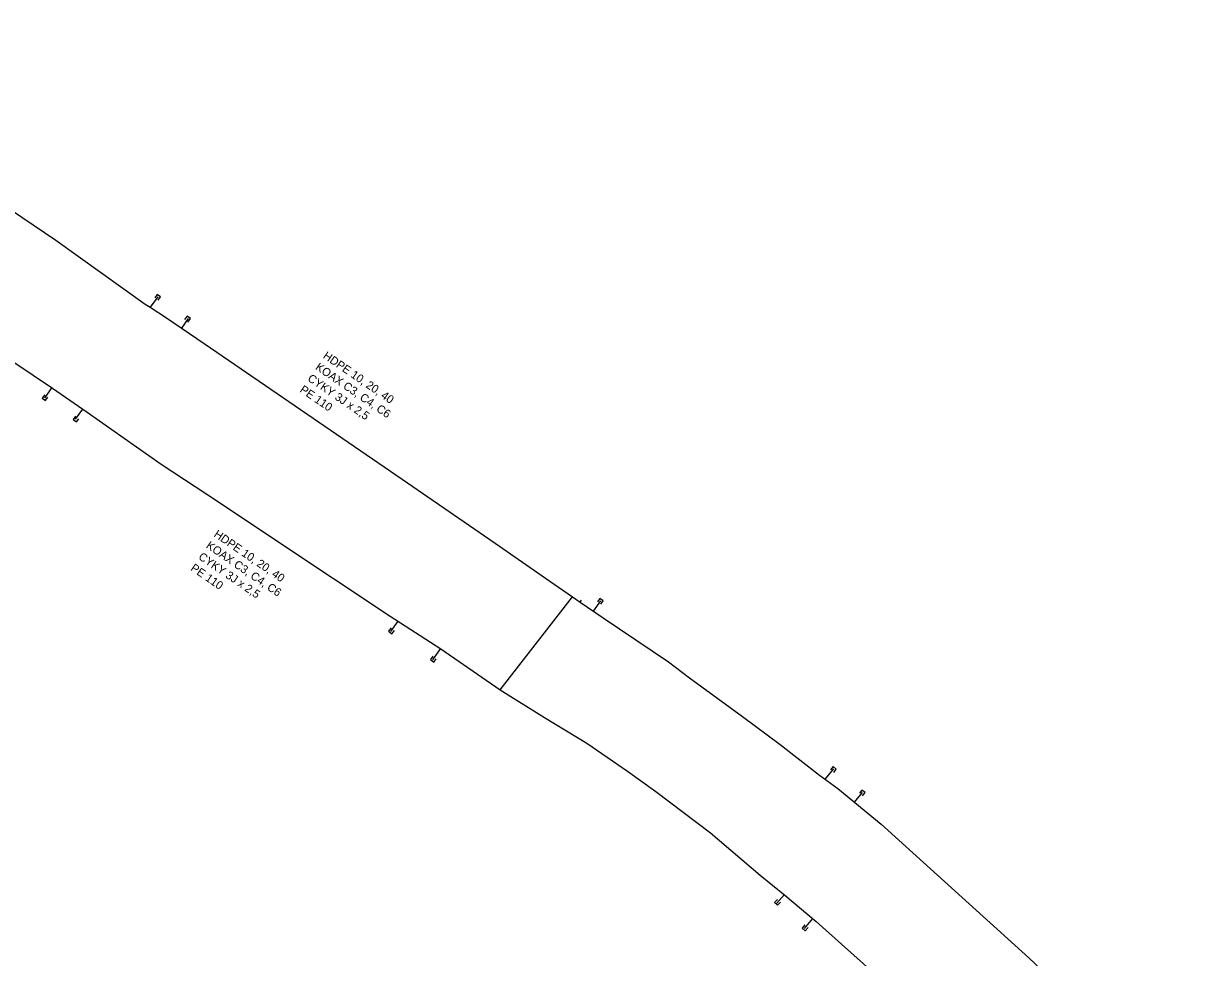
# Model space of a CAD drawing. Extents: x -651943 to -618711, y -1138561 to -1100552.
# Drawn here: x -641955 to -641849.2, y -1113561 to -1113475.7 of the extents above; entities that cross this region are included whole.
import ezdxf

# ---------------------------------------------------------------- set-up
doc = ezdxf.new("R2010")
doc.units = 0
for name, color, linetype in [('KT optika', 7, 'Continuous'), ('KT trasa', 7, 'Continuous'), ('KT zařízení', 7, 'Continuous')]:
    doc.layers.add(name, color=color, linetype=linetype)

# ---------------------------------------------------------------- blocks, each defined once
blk = doc.blocks.new('KKK_4')
at = {"layer": 'KT zařízení'}
for p, q in [((0.037, 0.037), (-0.038, 0.037)), ((0.037, -0.038), (0.037, 0.037)), ((-0.038, -0.038), (0.037, -0.038))]:
    blk.add_line(p, q, dxfattribs=at)
blk = doc.blocks.new('KKK_5')
at = {"layer": 'KT zařízení'}
for p, q in [((0.037, 0.037), (-0.038, 0.038)), ((0.037, -0.037), (0.037, 0.037)), ((-0.037, -0.037), (0.037, -0.037))]:
    blk.add_line(p, q, dxfattribs=at)
blk = doc.blocks.new('KKK_6')
at = {"layer": 'KT zařízení'}
for p, q in [((0.038, 0.038), (-0.038, 0.038)), ((0.038, -0.038), (0.038, 0.038)), ((-0.038, -0.037), (0.038, -0.038))]:
    blk.add_line(p, q, dxfattribs=at)
blk = doc.blocks.new('KKK_7')
at = {"layer": 'KT zařízení'}
for p, q in [((0.038, 0.037), (-0.038, 0.037)), ((0.038, -0.037), (0.038, 0.037)), ((-0.038, -0.038), (0.038, -0.037))]:
    blk.add_line(p, q, dxfattribs=at)
blk = doc.blocks.new('KKK_8')
at = {"layer": 'KT zařízení'}
for p, q in [((0.037, 0.037), (-0.038, 0.037)), ((0.038, -0.038), (0.037, 0.037)), ((-0.038, -0.037), (0.038, -0.038))]:
    blk.add_line(p, q, dxfattribs=at)
blk = doc.blocks.new('KKK_10')
at = {"layer": 'KT zařízení'}
for p, q in [((0.037, 0.037), (-0.037, 0.038)), ((0.037, -0.037), (0.037, 0.037)), ((-0.038, -0.037), (0.037, -0.037))]:
    blk.add_line(p, q, dxfattribs=at)
blk = doc.blocks.new('KKK_2')
at = {"layer": 'KT zařízení'}
for p, q in [((0.037, 0.038), (-0.037, 0.038)), ((0.037, -0.038), (0.037, 0.038)), ((-0.037, -0.038), (0.037, -0.038))]:
    blk.add_line(p, q, dxfattribs=at)
blk = doc.blocks.new('KKK_11')
at = {"layer": 'KT zařízení'}
for p, q in [((0.038, 0.037), (-0.037, 0.037)), ((0.038, -0.037), (0.038, 0.037)), ((-0.038, -0.037), (0.038, -0.037))]:
    blk.add_line(p, q, dxfattribs=at)

msp = doc.modelspace()

# ---------------------------------------------------------------- linework, layer by layer
at = {"layer": 'KT optika'}
for points in [[(-641981.59, -1113475.66), (-641978.35, -1113477.8), (-641973.39, -1113481.09), (-641965.85, -1113486.26), (-641958.24, -1113491.27), (-641951.99, -1113495.48), (-641943.83, -1113501.31), (-641943.42, -1113501.58)], [(-641980.53, -1113490.04), (-641975.1, -1113493.79), (-641970.07, -1113497.16), (-641964.3, -1113501.02), (-641959.29, -1113504.31), (-641952.31, -1113509), (-641949.13, -1113511.18), (-641942.39, -1113515.92), (-641937.14, -1113519.38), (-641931.83, -1113522.95), (-641921.48, -1113529.82), (-641916.84, -1113532.81), (-641911.44, -1113536.54)], [(-641943.38, -1113501.61), (-641941.89, -1113502.58), (-641938.46, -1113504.92), (-641933.44, -1113508.37), (-641920.38, -1113517.31), (-641911.88, -1113523.16), (-641906.9, -1113526.63), (-641904.82, -1113528.06)], [(-641911.44, -1113536.54), (-641904.82, -1113528.06)], [(-641904.82, -1113528.06), (-641904.13, -1113528.53)], [(-641904.13, -1113528.53), (-641902.04, -1113529.97), (-641896.07, -1113533.99), (-641894.16, -1113535.44), (-641889.3, -1113538.97), (-641885.87, -1113541.54), (-641882.27, -1113544.34), (-641880.61, -1113545.54), (-641876.66, -1113548.82), (-641872.16, -1113552.88), (-641863.18, -1113561.02), (-641860.34, -1113563.69), (-641857.88, -1113566.01), (-641856.08, -1113567.88), (-641849.41, -1113574.94)], [(-641911.44, -1113536.54), (-641907.38, -1113539.08), (-641903.51, -1113541.41), (-641899.81, -1113543.96), (-641897.22, -1113545.82), (-641892.23, -1113549.61), (-641887.7, -1113553.48), (-641885.43, -1113555.29), (-641882.57, -1113557.7), (-641877.1, -1113562.6), (-641871.4, -1113567.76), (-641866.6, -1113572.39), (-641861.74, -1113577.24), (-641857.57, -1113581.74), (-641851.66, -1113588.43), (-641849.2, -1113591.22)]]:
    msp.add_lwpolyline(points, dxfattribs=at)
at = {"layer": 'KT trasa'}
for points in [[(-641981.59, -1113475.66), (-641978.35, -1113477.8), (-641973.39, -1113481.09), (-641965.85, -1113486.26), (-641958.24, -1113491.27), (-641951.99, -1113495.48), (-641943.83, -1113501.31), (-641943.42, -1113501.58)], [(-641980.53, -1113490.04), (-641975.1, -1113493.79), (-641970.07, -1113497.16), (-641964.3, -1113501.02), (-641959.29, -1113504.31), (-641952.31, -1113509), (-641949.13, -1113511.18), (-641942.39, -1113515.92), (-641937.14, -1113519.38), (-641931.83, -1113522.95), (-641921.48, -1113529.82), (-641916.84, -1113532.81), (-641911.44, -1113536.54)], [(-641943.38, -1113501.61), (-641941.89, -1113502.58), (-641938.46, -1113504.92), (-641933.44, -1113508.37), (-641920.38, -1113517.31), (-641911.88, -1113523.16), (-641906.9, -1113526.63), (-641904.82, -1113528.06)], [(-641911.44, -1113536.54), (-641904.82, -1113528.06)], [(-641904.82, -1113528.06), (-641904.13, -1113528.53)], [(-641904.13, -1113528.53), (-641902.04, -1113529.97), (-641896.07, -1113533.99), (-641894.16, -1113535.44), (-641889.3, -1113538.97), (-641885.87, -1113541.54), (-641882.27, -1113544.34), (-641880.61, -1113545.54), (-641876.66, -1113548.82), (-641872.16, -1113552.88), (-641863.18, -1113561.02), (-641860.34, -1113563.69), (-641857.88, -1113566.01), (-641856.08, -1113567.88), (-641849.41, -1113574.94)], [(-641911.44, -1113536.54), (-641907.38, -1113539.08), (-641903.51, -1113541.41), (-641899.81, -1113543.96), (-641897.22, -1113545.82), (-641892.23, -1113549.61), (-641887.7, -1113553.48), (-641885.43, -1113555.29), (-641882.57, -1113557.7), (-641877.1, -1113562.6), (-641871.4, -1113567.76), (-641866.6, -1113572.39), (-641861.74, -1113577.24), (-641857.57, -1113581.74), (-641851.66, -1113588.43), (-641849.2, -1113591.22)]]:
    msp.add_lwpolyline(points, dxfattribs=at)
at = {"layer": 'KT zařízení'}
for points in [[(-641981.59, -1113475.66), (-641978.35, -1113477.8), (-641973.39, -1113481.09), (-641965.85, -1113486.26), (-641958.24, -1113491.27), (-641951.99, -1113495.48), (-641943.83, -1113501.31), (-641943.38, -1113501.61)], [(-641980.26, -1113490.24), (-641975.1, -1113493.79), (-641970.07, -1113497.16), (-641964.3, -1113501.02), (-641959.29, -1113504.31), (-641952.31, -1113509), (-641949.13, -1113511.18), (-641942.39, -1113515.92), (-641937.14, -1113519.38), (-641931.83, -1113522.95), (-641921.48, -1113529.82), (-641916.84, -1113532.81), (-641911.44, -1113536.54)], [(-641942.68, -1113500.65), (-641943.38, -1113501.61)], [(-641943.38, -1113501.61), (-641941.89, -1113502.58)], [(-641941.89, -1113502.58), (-641938.46, -1113504.92), (-641933.44, -1113508.37), (-641920.38, -1113517.31), (-641911.88, -1113523.16), (-641906.9, -1113526.63), (-641904.82, -1113528.06)], [(-641939.92, -1113502.64), (-641940.53, -1113503.51)], [(-641952.99, -1113509.9), (-641952.35, -1113508.97)], [(-641950.19, -1113511.84), (-641949.54, -1113510.9)], [(-641911.44, -1113536.54), (-641904.82, -1113528.06)], [(-641904.82, -1113528.06), (-641904.13, -1113528.53)], [(-641904.13, -1113528.53), (-641904.01, -1113528.36)], [(-641904.13, -1113528.53), (-641902.04, -1113529.97), (-641896.07, -1113533.99), (-641894.16, -1113535.44), (-641889.3, -1113538.97), (-641885.87, -1113541.54), (-641882.27, -1113544.34), (-641880.61, -1113545.54), (-641876.66, -1113548.82), (-641872.16, -1113552.88), (-641863.18, -1113561.02), (-641860.34, -1113563.69), (-641857.88, -1113566.01), (-641856.08, -1113567.88), (-641849.41, -1113574.94)], [(-641902.28, -1113528.42), (-641902.94, -1113529.35)], [(-641921.4, -1113531.21), (-641920.76, -1113530.28)], [(-641917.57, -1113533.8), (-641916.87, -1113532.79)], [(-641911.44, -1113536.54), (-641907.38, -1113539.08), (-641903.51, -1113541.41), (-641899.81, -1113543.96), (-641897.22, -1113545.82), (-641892.23, -1113549.61), (-641887.7, -1113553.48), (-641885.43, -1113555.29), (-641882.57, -1113557.7), (-641877.1, -1113562.6), (-641871.4, -1113567.76), (-641866.6, -1113572.39), (-641861.74, -1113577.24), (-641857.57, -1113581.74), (-641851.66, -1113588.43), (-641849.2, -1113591.22)], [(-641881.77, -1113544.7), (-641880.98, -1113543.75)], [(-641879.08, -1113546.81), (-641878.35, -1113545.91)], [(-641886.19, -1113556.06), (-641885.48, -1113555.25)], [(-641883.65, -1113558.33), (-641882.88, -1113557.44)]]:
    msp.add_lwpolyline(points, dxfattribs=at)

# ---------------------------------------------------------------- block references
for name, p, xscale, yscale, rotation in [('KKK_11', (-641942.71, -1113500.7), 4.999979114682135, 4.999979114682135, 54.73178628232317), ('KKK_11', (-641939.98, -1113502.69), 4.999979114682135, 4.999979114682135, 54.73178628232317), ('KKK_4', (-641952.98, -1113509.87), 4.999978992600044, 4.9999789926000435, -126.77448783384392), ('KKK_5', (-641950.16, -1113511.82), 4.999993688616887, 4.999993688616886, -127.63863943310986), ('KKK_2', (-641902.3, -1113528.46), 5.000015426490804, 5.000015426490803, 54.765405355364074), ('KKK_6', (-641921.35, -1113531.15), 5.000006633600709, 5.000006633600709, -127.62572296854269), ('KKK_7', (-641917.53, -1113533.74), 4.9999938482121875, 4.9999938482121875, -127.14833648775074), ('KKK_10', (-641881.01, -1113543.82), 4.999998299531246, 4.999998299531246, 51.9871414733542), ('KKK_10', (-641878.37, -1113545.96), 4.999998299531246, 4.999998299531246, 51.9871414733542), ('KKK_8', (-641886.11, -1113555.96), 4.999992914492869, 4.999992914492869, -133.12212255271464), ('KKK_8', (-641883.59, -1113558.28), 4.999994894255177, 4.999994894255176, -131.38817253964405)]:
    msp.add_blockref(name, p, dxfattribs=dict(at, xscale=xscale, yscale=yscale, rotation=rotation))

# ---------------------------------------------------------------- texts
for s, p in [('HDPE 10, 20, 40', (-641927.67, -1113506.2)), ('KOAX C3, C4, C6', (-641928.37, -1113507.23)), ('CYKY 3J x 2,5', (-641929.08, -1113508.26)), ('PE 110', (-641929.79, -1113509.29)), ('HDPE 10, 20, 40', (-641937.64, -1113522.5)), ('KOAX C3, C4, C6', (-641938.35, -1113523.53)), ('CYKY 3J x 2,5', (-641939.05, -1113524.55)), ('PE 110', (-641939.76, -1113525.58))]:
    msp.add_text(s, height=0.75, rotation=325.5625, dxfattribs=at).set_placement(p)

doc.saveas('drawing.dxf')
